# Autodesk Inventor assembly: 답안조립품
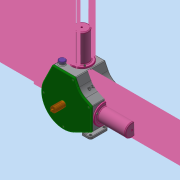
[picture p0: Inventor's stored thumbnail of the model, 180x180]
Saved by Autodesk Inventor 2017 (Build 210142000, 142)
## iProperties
Part Number: 답안조립품
Material: 일반
Document SubType Name: Assembly
Designer: MRC
Mass: 3748.67 g
Surface Area: 4101.75 cm^2
Volume: 1119.43 cm^3
Density: 3.34872 g/cm^3
Author: MRC
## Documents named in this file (13)
- C:\Users\MRC\Desktop\611109V1007\답안조립품.iam
- C:\Users\MRC\Desktop\611109V1007\너트 M3.ipt
- C:\Users\MRC\Desktop\611109V1007\베어링 20 x 37 x 9.ipt
- C:\Users\MRC\Desktop\611109V1007\본체.ipt
- C:\Users\MRC\Desktop\611109V1007\볼트 M3 x 12.ipt
- C:\Users\MRC\Desktop\611109V1007\실린더.ipt
- C:\Users\MRC\Desktop\611109V1007\앞커버.ipt
- C:\Users\MRC\Desktop\611109V1007\축.ipt
- C:\Users\MRC\Desktop\611109V1007\측정게이지.ipt
- C:\Users\MRC\Desktop\611109V1007\커넥팅로드 캡.ipt
- C:\Users\MRC\Desktop\611109V1007\커넥팅로드.ipt
- C:\Users\MRC\Desktop\611109V1007\피스톤 핀.ipt
- C:\Users\MRC\Desktop\611109V1007\피스톤.ipt
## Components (4 placed, 2 different names)
1. 피스톤 핀:1
2. 피스톤:1
3. 피스톤 핀:2
4. 피스톤:2
